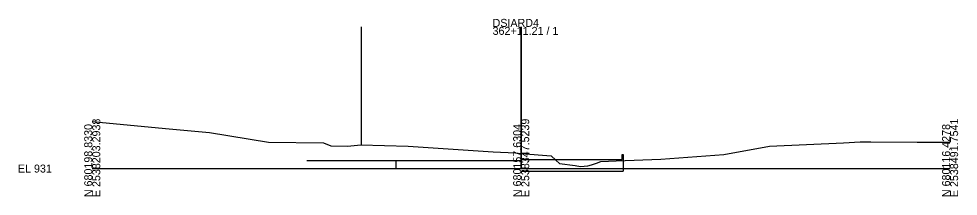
# Model space of a CAD drawing. Extents: x -26 to 1603, y -30 to 14537.
# Drawn here: x 1274.3 to 1602.8, y 2990.3 to 3052.5 of the extents above; entities that cross this region are included whole.
import ezdxf

# ---------------------------------------------------------------- set-up
doc = ezdxf.new("R2010")
doc.units = 0
for name, color, linetype in [('DESIGN - SCRATCH - User 5', 7, 'Continuous'), ('DESIGN - SCRATCH - User 6 - Structures', 7, 'Continuous'), ('DESIGN - SHEET - Light Grid', 7, 'Continuous'), ('SURVEY - GROUND - Top of Ground', 7, 'Continuous')]:
    doc.layers.add(name, color=color, linetype=linetype)

msp = doc.modelspace()

# ---------------------------------------------------------------- linework, layer by layer
at = {"layer": 'DESIGN - SCRATCH - User 5'}
for p, q in [((1394.04, 3049.62), (1394.04, 3008.25)), ((1450, 3049.62), (1450, 3000)), ((1450, 3002.68), (1375, 3002.68)), ((1406.17, 3002.68), (1406.17, 3000))]:
    msp.add_line(p, q, dxfattribs=at)
at = {"layer": 'DESIGN - SCRATCH - User 6 - Structures'}
for p, q in [((1450, 3003.12), (1485.31, 3003.12)), ((1485.64, 3004.91), (1485.64, 2999.12)), ((1450, 2999.12), (1485.64, 2999.12))]:
    msp.add_line(p, q, dxfattribs=at)
msp.add_lwpolyline([(1485.31, 3003.12), (1485.31, 3004.91), (1485.64, 3004.91)], dxfattribs=at)
at = {"layer": 'DESIGN - SHEET - Light Grid'}
for p, q in [((1450, 3000), (1450, 3049.62)), ((1300, 3000), (1450, 3000)), ((1450, 3000), (1600, 3000))]:
    msp.add_line(p, q, dxfattribs=at)
at = {"layer": 'SURVEY - GROUND - Top of Ground'}
msp.add_lwpolyline([(1300, 3016.54), (1310.9, 3015.43), (1326.91, 3013.92), (1341.06, 3012.65), (1361.64, 3009.28), (1380.82, 3009.02), (1383.39, 3007.94), (1389.21, 3007.8), (1393.98, 3008.26), (1410.53, 3007.79), (1440.19, 3005.91), (1447.96, 3005.51), (1450, 3005.33), (1460.52, 3004.4), (1462.17, 3002.91), (1463.45, 3001.8), (1468.89, 3001.05), (1470.72, 3000.77), (1473.32, 3000.94), (1474.56, 3001.31), (1476.29, 3001.93), (1477.91, 3002.47), (1483.18, 3002.71), (1498.87, 3003.25), (1520.82, 3004.92), (1536.79, 3007.9), (1562.71, 3009.04), (1568.55, 3009.36), (1571.17, 3009.39), (1572.3, 3009.38), (1588.45, 3009.27), (1600, 3009.23)], dxfattribs=at)

# ---------------------------------------------------------------- texts
at = {"layer": 'DESIGN - SHEET - Light Grid'}
for s, p in [('DSIARD4', (1440, 3049.62)), ('362+11.21 / 1', (1440, 3046.82)), ('EL 931', (1274, 2998.6))]:
    msp.add_text(s, height=2.8, dxfattribs=at).set_placement(p)
for s, p in [('E 2538203.2938', (1302.8, 2990)), ('E 2538347.5239', (1452.8, 2990)), ('E 2538491.7541', (1602.8, 2990)), ('N 680198.8330', (1300, 2990)), ('N 680157.6304', (1450, 2990)), ('N 680116.4278', (1600, 2990))]:
    msp.add_text(s, height=2.8, rotation=90, dxfattribs=at).set_placement(p)

doc.saveas('drawing.dxf')
